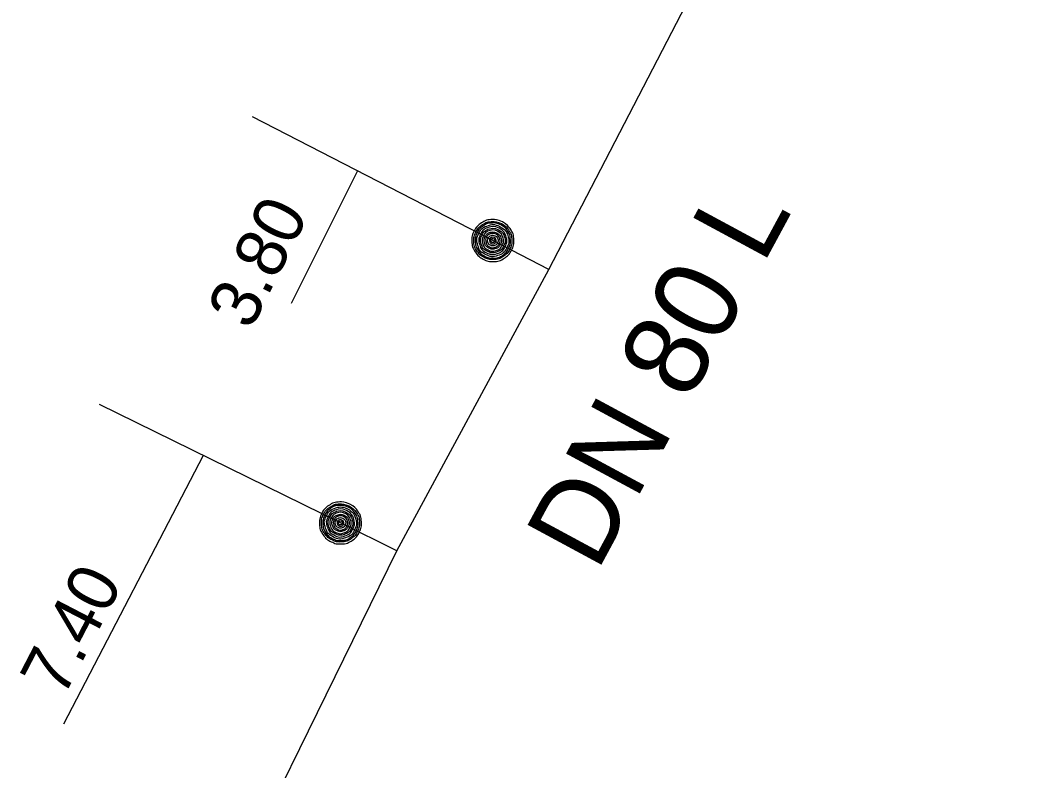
# Model space of a CAD drawing. Extents: x -820257 to -819974, y -1070894 to -1070484.
# Drawn here: x -820074.82 to -820050.97, y -1070546.62 to -1070528.73 of the extents above; entities that cross this region are included whole.
import ezdxf

# ---------------------------------------------------------------- set-up
doc = ezdxf.new("R2010")
doc.units = 0
for name, color, linetype in [('Oměrka vodovodu', 7, 'Continuous'), ('Oměrka-text', 7, 'Continuous'), ('Přípojka vodovodu', 7, 'Continuous'), ('Přípojkový uzávěr', 7, 'Continuous'), ('Roz-řad', 7, 'Continuous'), ('Roz-řad-popis základní', 7, 'Continuous')]:
    doc.layers.add(name, color=color, linetype=linetype)

msp = doc.modelspace()

# ---------------------------------------------------------------- linework, layer by layer
at = {"layer": 'Oměrka vodovodu'}
for p, q in [((-820066.767, -1070532.333), (-820068.348, -1070535.491)), ((-820070.453, -1070539.117), (-820073.779, -1070545.525))]:
    msp.add_line(p, q, dxfattribs=at)
at = {"layer": 'Přípojka vodovodu'}
for points in [[(-820062.208, -1070534.681), (-820063.543, -1070533.994), (-820069.275, -1070531.041)], [(-820065.83, -1070541.39), (-820067.176, -1070540.728), (-820072.921, -1070537.903)]]:
    msp.add_lwpolyline(points, dxfattribs=at)
at = {"layer": 'Přípojkový uzávěr'}
for points in [[(-820063.314, -1070533.549), (-820063.202, -1070533.606), (-820063.125, -1070533.718), (-820063.048, -1070533.831), (-820063.043, -1070533.969), (-820063.038, -1070534.106), (-820063.098, -1070534.223), (-820063.158, -1070534.338), (-820063.271, -1070534.414), (-820063.384, -1070534.489), (-820063.52, -1070534.493), (-820063.656, -1070534.497), (-820063.772, -1070534.438), (-820063.887, -1070534.378), (-820063.963, -1070534.265), (-820064.038, -1070534.152), (-820064.043, -1070534.016), (-820064.047, -1070533.88), (-820063.987, -1070533.765), (-820063.927, -1070533.649), (-820063.813, -1070533.572), (-820063.698, -1070533.496), (-820063.562, -1070533.493), (-820063.426, -1070533.491), (-820063.314, -1070533.549)], [(-820063.335, -1070533.59), (-820063.437, -1070533.538), (-820063.56, -1070533.54), (-820063.683, -1070533.543), (-820063.787, -1070533.612), (-820063.891, -1070533.681), (-820063.946, -1070533.786), (-820063.999, -1070533.891), (-820063.996, -1070534.014), (-820063.992, -1070534.137), (-820063.923, -1070534.24), (-820063.855, -1070534.342), (-820063.75, -1070534.396), (-820063.645, -1070534.45), (-820063.522, -1070534.447), (-820063.398, -1070534.443), (-820063.296, -1070534.374), (-820063.194, -1070534.306), (-820063.14, -1070534.201), (-820063.086, -1070534.096), (-820063.09, -1070533.971), (-820063.095, -1070533.846), (-820063.164, -1070533.744), (-820063.234, -1070533.643), (-820063.335, -1070533.59)], [(-820063.351, -1070533.621), (-820063.257, -1070533.669), (-820063.193, -1070533.763), (-820063.129, -1070533.857), (-820063.124, -1070533.972), (-820063.12, -1070534.088), (-820063.17, -1070534.186), (-820063.22, -1070534.283), (-820063.315, -1070534.346), (-820063.409, -1070534.409), (-820063.523, -1070534.413), (-820063.638, -1070534.416), (-820063.735, -1070534.366), (-820063.831, -1070534.316), (-820063.895, -1070534.221), (-820063.959, -1070534.126), (-820063.962, -1070534.013), (-820063.965, -1070533.899), (-820063.915, -1070533.802), (-820063.865, -1070533.704), (-820063.769, -1070533.64), (-820063.673, -1070533.577), (-820063.559, -1070533.575), (-820063.445, -1070533.572), (-820063.351, -1070533.621)], [(-820063.372, -1070533.66), (-820063.511, -1070533.588), (-820063.658, -1070533.636), (-820063.805, -1070533.684), (-820063.876, -1070533.822), (-820063.947, -1070533.96), (-820063.9, -1070534.108), (-820063.852, -1070534.256), (-820063.715, -1070534.326), (-820063.576, -1070534.398), (-820063.428, -1070534.351), (-820063.28, -1070534.304), (-820063.209, -1070534.166), (-820063.138, -1070534.027), (-820063.185, -1070533.879), (-820063.231, -1070533.732), (-820063.372, -1070533.66)], [(-820063.393, -1070533.7), (-820063.271, -1070533.763), (-820063.23, -1070533.892), (-820063.189, -1070534.021), (-820063.251, -1070534.142), (-820063.314, -1070534.263), (-820063.443, -1070534.305), (-820063.572, -1070534.346), (-820063.693, -1070534.284), (-820063.815, -1070534.221), (-820063.856, -1070534.092), (-820063.897, -1070533.963), (-820063.835, -1070533.842), (-820063.772, -1070533.721), (-820063.643, -1070533.679), (-820063.514, -1070533.638), (-820063.393, -1070533.7)], [(-820063.411, -1070533.736), (-820063.518, -1070533.681), (-820063.631, -1070533.717), (-820063.745, -1070533.754), (-820063.8, -1070533.86), (-820063.854, -1070533.966), (-820063.818, -1070534.08), (-820063.782, -1070534.194), (-820063.675, -1070534.249), (-820063.569, -1070534.303), (-820063.455, -1070534.267), (-820063.341, -1070534.231), (-820063.286, -1070534.124), (-820063.232, -1070534.018), (-820063.268, -1070533.904), (-820063.304, -1070533.791), (-820063.411, -1070533.736)], [(-820063.429, -1070533.771), (-820063.335, -1070533.819), (-820063.304, -1070533.917), (-820063.273, -1070534.016), (-820063.321, -1070534.108), (-820063.368, -1070534.2), (-820063.466, -1070534.232), (-820063.565, -1070534.263), (-820063.657, -1070534.215), (-820063.749, -1070534.168), (-820063.781, -1070534.07), (-820063.812, -1070533.971), (-820063.765, -1070533.879), (-820063.717, -1070533.787), (-820063.619, -1070533.755), (-820063.521, -1070533.723), (-820063.429, -1070533.771)], [(-820063.45, -1070533.812), (-820063.525, -1070533.774), (-820063.605, -1070533.799), (-820063.685, -1070533.825), (-820063.723, -1070533.9), (-820063.762, -1070533.975), (-820063.736, -1070534.055), (-820063.711, -1070534.135), (-820063.636, -1070534.173), (-820063.561, -1070534.212), (-820063.481, -1070534.186), (-820063.401, -1070534.161), (-820063.362, -1070534.086), (-820063.324, -1070534.011), (-820063.349, -1070533.931), (-820063.375, -1070533.851), (-820063.45, -1070533.812)], [(-820063.466, -1070533.843), (-820063.403, -1070533.875), (-820063.382, -1070533.941), (-820063.361, -1070534.007), (-820063.393, -1070534.07), (-820063.425, -1070534.132), (-820063.492, -1070534.153), (-820063.558, -1070534.175), (-820063.62, -1070534.143), (-820063.682, -1070534.11), (-820063.704, -1070534.044), (-820063.725, -1070533.978), (-820063.693, -1070533.916), (-820063.66, -1070533.853), (-820063.594, -1070533.832), (-820063.528, -1070533.811), (-820063.466, -1070533.843)], [(-820063.486, -1070533.882), (-820063.532, -1070533.858), (-820063.581, -1070533.874), (-820063.63, -1070533.89), (-820063.654, -1070533.936), (-820063.677, -1070533.982), (-820063.662, -1070534.032), (-820063.646, -1070534.081), (-820063.6, -1070534.104), (-820063.554, -1070534.128), (-820063.504, -1070534.112), (-820063.455, -1070534.097), (-820063.431, -1070534.051), (-820063.408, -1070534.005), (-820063.423, -1070533.955), (-820063.439, -1070533.906), (-820063.486, -1070533.882)], [(-820063.507, -1070533.924), (-820063.478, -1070533.939), (-820063.468, -1070533.969), (-820063.458, -1070533.999), (-820063.474, -1070534.029), (-820063.488, -1070534.058), (-820063.519, -1070534.068), (-820063.549, -1070534.078), (-820063.579, -1070534.063), (-820063.607, -1070534.048), (-820063.617, -1070534.017), (-820063.627, -1070533.986), (-820063.612, -1070533.957), (-820063.597, -1070533.928), (-820063.567, -1070533.918), (-820063.536, -1070533.909), (-820063.507, -1070533.924)], [(-820063.522, -1070533.952), (-820063.539, -1070533.943), (-820063.557, -1070533.948), (-820063.575, -1070533.954), (-820063.585, -1070533.972), (-820063.594, -1070533.989), (-820063.588, -1070534.008), (-820063.582, -1070534.026), (-820063.564, -1070534.035), (-820063.547, -1070534.044), (-820063.528, -1070534.038), (-820063.51, -1070534.032), (-820063.501, -1070534.015), (-820063.492, -1070533.997), (-820063.498, -1070533.979), (-820063.504, -1070533.961), (-820063.522, -1070533.952)], [(-820066.955, -1070540.279), (-820066.842, -1070540.335), (-820066.764, -1070540.445), (-820066.685, -1070540.556), (-820066.677, -1070540.694), (-820066.669, -1070540.832), (-820066.727, -1070540.949), (-820066.785, -1070541.066), (-820066.896, -1070541.143), (-820067.008, -1070541.221), (-820067.144, -1070541.227), (-820067.28, -1070541.234), (-820067.397, -1070541.176), (-820067.513, -1070541.119), (-820067.591, -1070541.008), (-820067.669, -1070540.896), (-820067.675, -1070540.76), (-820067.682, -1070540.624), (-820067.625, -1070540.508), (-820067.567, -1070540.39), (-820067.453, -1070540.312), (-820067.34, -1070540.234), (-820067.205, -1070540.228), (-820067.069, -1070540.223), (-820066.955, -1070540.279)], [(-820066.976, -1070540.321), (-820067.079, -1070540.271), (-820067.202, -1070540.275), (-820067.325, -1070540.28), (-820067.427, -1070540.351), (-820067.53, -1070540.422), (-820067.583, -1070540.528), (-820067.634, -1070540.634), (-820067.628, -1070540.757), (-820067.623, -1070540.88), (-820067.552, -1070540.981), (-820067.481, -1070541.083), (-820067.376, -1070541.134), (-820067.27, -1070541.187), (-820067.147, -1070541.181), (-820067.023, -1070541.175), (-820066.922, -1070541.104), (-820066.821, -1070541.034), (-820066.769, -1070540.928), (-820066.717, -1070540.822), (-820066.724, -1070540.697), (-820066.731, -1070540.572), (-820066.802, -1070540.472), (-820066.874, -1070540.372), (-820066.976, -1070540.321)], [(-820066.991, -1070540.352), (-820066.896, -1070540.399), (-820066.83, -1070540.491), (-820066.765, -1070540.584), (-820066.758, -1070540.699), (-820066.751, -1070540.815), (-820066.8, -1070540.913), (-820066.848, -1070541.011), (-820066.941, -1070541.076), (-820067.034, -1070541.141), (-820067.149, -1070541.147), (-820067.263, -1070541.152), (-820067.361, -1070541.104), (-820067.458, -1070541.056), (-820067.524, -1070540.962), (-820067.589, -1070540.868), (-820067.595, -1070540.755), (-820067.6, -1070540.641), (-820067.552, -1070540.544), (-820067.503, -1070540.445), (-820067.408, -1070540.379), (-820067.314, -1070540.314), (-820067.2, -1070540.309), (-820067.086, -1070540.305), (-820066.991, -1070540.352)], [(-820067.011, -1070540.391), (-820067.151, -1070540.322), (-820067.297, -1070540.373), (-820067.444, -1070540.423), (-820067.512, -1070540.563), (-820067.581, -1070540.702), (-820067.531, -1070540.849), (-820067.48, -1070540.996), (-820067.342, -1070541.064), (-820067.202, -1070541.133), (-820067.055, -1070541.083), (-820066.908, -1070541.033), (-820066.839, -1070540.894), (-820066.771, -1070540.754), (-820066.82, -1070540.607), (-820066.87, -1070540.461), (-820067.011, -1070540.391)], [(-820067.031, -1070540.432), (-820066.908, -1070540.493), (-820066.865, -1070540.621), (-820066.822, -1070540.749), (-820066.882, -1070540.871), (-820066.942, -1070540.994), (-820067.07, -1070541.037), (-820067.199, -1070541.081), (-820067.321, -1070541.021), (-820067.444, -1070540.961), (-820067.487, -1070540.832), (-820067.531, -1070540.704), (-820067.471, -1070540.582), (-820067.41, -1070540.46), (-820067.282, -1070540.416), (-820067.154, -1070540.372), (-820067.031, -1070540.432)], [(-820067.049, -1070540.468), (-820067.157, -1070540.415), (-820067.269, -1070540.453), (-820067.382, -1070540.492), (-820067.435, -1070540.599), (-820067.488, -1070540.707), (-820067.45, -1070540.82), (-820067.411, -1070540.933), (-820067.303, -1070540.986), (-820067.196, -1070541.038), (-820067.083, -1070541), (-820066.97, -1070540.961), (-820066.917, -1070540.854), (-820066.864, -1070540.747), (-820066.902, -1070540.634), (-820066.941, -1070540.521), (-820067.049, -1070540.468)], [(-820067.066, -1070540.503), (-820066.972, -1070540.55), (-820066.939, -1070540.648), (-820066.906, -1070540.745), (-820066.952, -1070540.839), (-820066.997, -1070540.932), (-820067.095, -1070540.965), (-820067.193, -1070540.998), (-820067.286, -1070540.952), (-820067.379, -1070540.907), (-820067.412, -1070540.809), (-820067.446, -1070540.711), (-820067.4, -1070540.618), (-820067.354, -1070540.525), (-820067.257, -1070540.491), (-820067.16, -1070540.457), (-820067.066, -1070540.503)], [(-820067.086, -1070540.545), (-820067.162, -1070540.508), (-820067.241, -1070540.535), (-820067.321, -1070540.562), (-820067.358, -1070540.638), (-820067.395, -1070540.713), (-820067.368, -1070540.793), (-820067.341, -1070540.872), (-820067.266, -1070540.91), (-820067.19, -1070540.947), (-820067.111, -1070540.92), (-820067.031, -1070540.893), (-820066.994, -1070540.817), (-820066.956, -1070540.741), (-820066.983, -1070540.662), (-820067.01, -1070540.582), (-820067.086, -1070540.545)], [(-820067.102, -1070540.576), (-820067.038, -1070540.607), (-820067.016, -1070540.673), (-820066.994, -1070540.739), (-820067.025, -1070540.802), (-820067.056, -1070540.865), (-820067.122, -1070540.887), (-820067.188, -1070540.909), (-820067.25, -1070540.878), (-820067.313, -1070540.847), (-820067.336, -1070540.782), (-820067.358, -1070540.716), (-820067.327, -1070540.653), (-820067.296, -1070540.59), (-820067.23, -1070540.567), (-820067.165, -1070540.545), (-820067.102, -1070540.576)], [(-820067.121, -1070540.616), (-820067.167, -1070540.593), (-820067.216, -1070540.61), (-820067.265, -1070540.626), (-820067.288, -1070540.673), (-820067.311, -1070540.719), (-820067.294, -1070540.768), (-820067.277, -1070540.817), (-820067.231, -1070540.84), (-820067.184, -1070540.863), (-820067.135, -1070540.846), (-820067.086, -1070540.83), (-820067.064, -1070540.783), (-820067.041, -1070540.737), (-820067.057, -1070540.688), (-820067.074, -1070540.639), (-820067.121, -1070540.616)], [(-820067.142, -1070540.658), (-820067.112, -1070540.672), (-820067.102, -1070540.702), (-820067.091, -1070540.732), (-820067.106, -1070540.762), (-820067.12, -1070540.791), (-820067.151, -1070540.802), (-820067.181, -1070540.813), (-820067.211, -1070540.798), (-820067.24, -1070540.784), (-820067.25, -1070540.753), (-820067.26, -1070540.722), (-820067.246, -1070540.693), (-820067.232, -1070540.663), (-820067.201, -1070540.653), (-820067.171, -1070540.643), (-820067.142, -1070540.658)], [(-820067.155, -1070540.686), (-820067.173, -1070540.677), (-820067.191, -1070540.683), (-820067.209, -1070540.689), (-820067.218, -1070540.707), (-820067.227, -1070540.725), (-820067.221, -1070540.743), (-820067.214, -1070540.761), (-820067.197, -1070540.77), (-820067.179, -1070540.779), (-820067.161, -1070540.772), (-820067.143, -1070540.766), (-820067.134, -1070540.748), (-820067.125, -1070540.73), (-820067.131, -1070540.712), (-820067.137, -1070540.695), (-820067.155, -1070540.686)]]:
    msp.add_open_spline(points, degree=3, dxfattribs=at)
at = {"layer": 'Roz-řad'}
msp.add_lwpolyline([(-820073.442, -1070556.519), (-820070.878, -1070551.68), (-820065.83, -1070541.39), (-820062.208, -1070534.681), (-820056.904, -1070524.441), (-820050.972, -1070512.997)], dxfattribs=at)

# ---------------------------------------------------------------- texts
at = {"layer": 'Oměrka-text'}
for s, rotation, p in [(' 3.80', 63.4059, (-820069.52, -1070536.557)), (' 7.40', 62.5689, (-820073.996, -1070545.323))]:
    msp.add_text(s, height=1.2, rotation=rotation, dxfattribs=at).set_placement(p)
at = {"layer": 'Roz-řad-popis základní'}
msp.add_text('DN 80 L', height=2, rotation=61.6366, dxfattribs=at).set_placement((-820061.058, -1070541.917))

doc.saveas('drawing.dxf')
